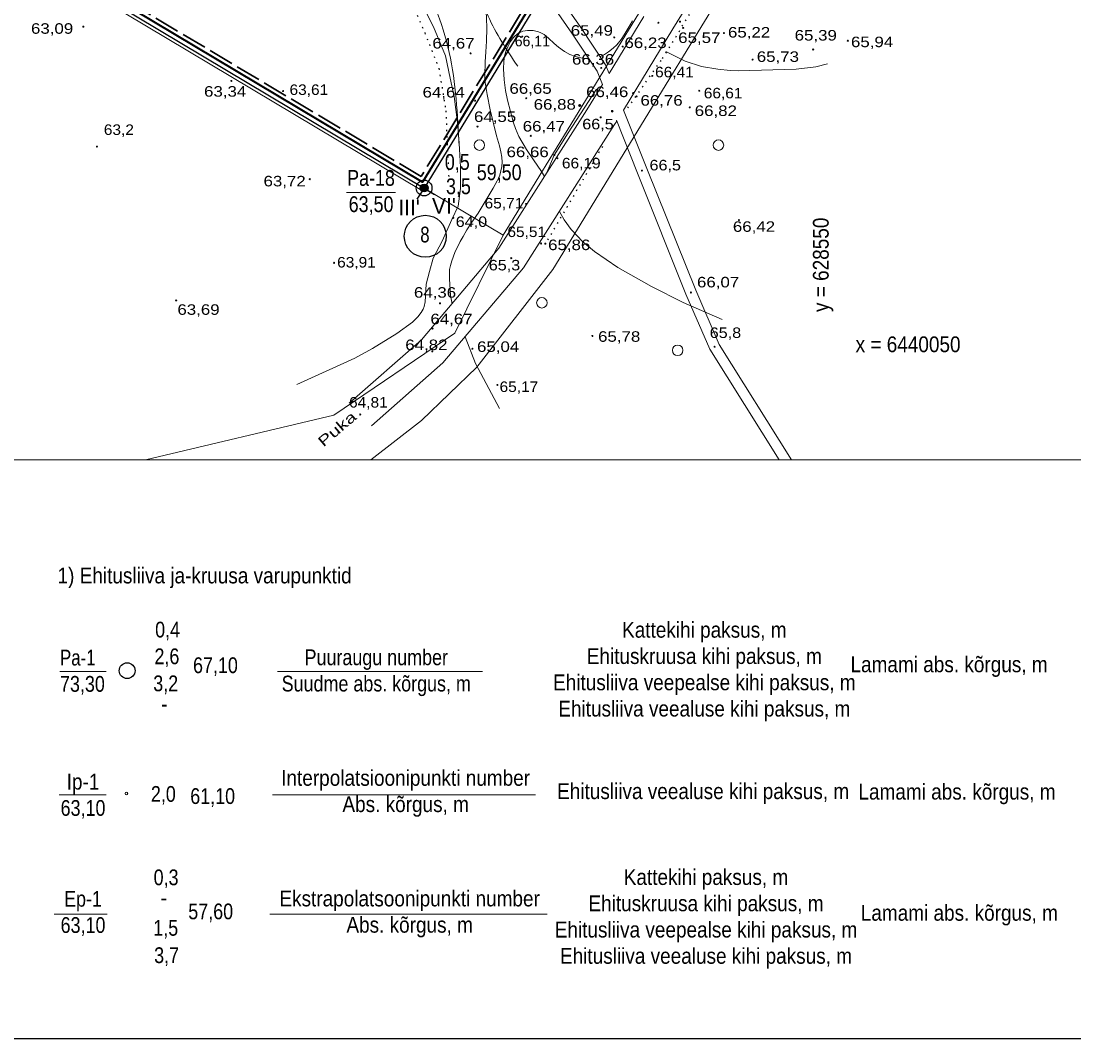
# Model space of a CAD drawing. Extents: x 628176 to 629009, y 6439913 to 6440496.
# Drawn here: x 628397.5 to 628597.9, y 6439918.5 to 6440112.2 of the extents above; entities that cross this region are included whole.
import ezdxf
from ezdxf.enums import TextEntityAlignment as Align

# ---------------------------------------------------------------- set-up
doc = ezdxf.new("R2010")
doc.units = 0
doc.header["$LTSCALE"] = 0.8
doc.header["$PDMODE"] = 32
doc.header["$PDSIZE"] = 0.4
for name, pattern in [('DOTTED', [1.5, 0.3, -1.2]), ('LONG_DASHED', [7.5, 6, -1.5]), ('MEDIUM_DASHED', [4.5, 3, -1.5])]:
    doc.linetypes.add(name, pattern=pattern)
for name, color, linetype, lineweight in [('1', 7, 'Continuous', 13), ('10', 7, 'Continuous', 25), ('11', 7, 'Continuous', 13), ('12', 7, 'Continuous', 13), ('14', 7, 'Continuous', 25), ('16', 7, 'Continuous', 13), ('21', 7, 'MEDIUM_DASHED', 35), ('3', 7, 'Continuous', 13), ('50', 7, 'Continuous', 13), ('6', 7, 'Continuous', 13)]:
    doc.layers.add(name, color=color, linetype=linetype, lineweight=lineweight)
doc.layers.add('4', color=7, linetype='Continuous')

msp = doc.modelspace()

# ---------------------------------------------------------------- hatches: boundary and pattern name
at = {"layer": '1'}
for points in [[(628409.4344, 6440111.0968, 1), (628409.2344, 6440111.0968, 1)], [(628518.8892, 6440111.8299, 1), (628518.6892, 6440111.8299, 1)], [(628523.0029, 6440112.0418, 1), (628522.8029, 6440112.0418, 1)], [(628523.6039, 6440110.8596, 1), (628523.4039, 6440110.8596, 1)], [(628492.973, 6440109.1947, 1), (628492.773, 6440109.1947, 1)], [(628510.4901, 6440109.0442, 1), (628510.2901, 6440109.0442, 1)], [(628531.3555, 6440109.875, 1), (628531.1555, 6440109.875, 1)], [(628554.9507, 6440108.4224, 1), (628554.7507, 6440108.4224, 1)], [(628512.0944, 6440107.305, 1), (628511.8944, 6440107.305, 1)], [(628548.348, 6440106.7428, 1), (628548.148, 6440106.7428, 1)], [(628483.1387, 6440106.0153, 1), (628482.9387, 6440106.0153, 1)], [(628536.8173, 6440104.8325, 1), (628536.6173, 6440104.8325, 1)], [(628508.02, 6440103.2332, 1), (628507.82, 6440103.2332, 1)], [(628437.6027, 6440100.7657, 1), (628437.4027, 6440100.7657, 1)], [(628517.7301, 6440101.7257, 1), (628517.5301, 6440101.7257, 1)], [(628447.4419, 6440098.8264, 1), (628447.2419, 6440098.8264, 1)], [(628514.0625, 6440098.4337, 1), (628513.8625, 6440098.4337, 1)], [(628526.6704, 6440098.8894, 1), (628526.4704, 6440098.8894, 1)], [(628483.9966, 6440097.0016, 1), (628483.7966, 6440097.0016, 1)], [(628493.7415, 6440097.4794, 1), (628493.5415, 6440097.4794, 1)], [(628514.7413, 6440097.8113, 1), (628514.5413, 6440097.8113, 1)], [(628503.9057, 6440096.0814, 1), (628503.7057, 6440096.0814, 1)], [(628510.1499, 6440094.9999, 1), (628509.8499, 6440094.9999, 1)], [(628524.8585, 6440095.7336, 1), (628524.6585, 6440095.7336, 1)], [(628507.9065, 6440093.8416, 1), (628507.7065, 6440093.8416, 1)], [(628484.4614, 6440092.0725, 1), (628484.2614, 6440092.0725, 1)], [(628494.6041, 6440090.3159, 1), (628494.4041, 6440090.3159, 1)], [(628412.0191, 6440088.2674, 1), (628411.8191, 6440088.2674, 1)], [(628499.0777, 6440086.6428, 1), (628498.8777, 6440086.6428, 1)], [(628499.6637, 6440086.0555, 1), (628499.4637, 6440086.0555, 1)], [(628515.7505, 6440083.7074, 1), (628515.5505, 6440083.7074, 1)], [(628452.5166, 6440082.0727, 1), (628452.3166, 6440082.0727, 1)], [(628493.6983, 6440077.3653, 1), (628493.4983, 6440077.3653, 1)], [(628479.858, 6440074.712, 1), (628479.658, 6440074.712, 1)], [(628534.2109, 6440074.2868, 1), (628534.0109, 6440074.2868, 1)], [(628496.5678, 6440069.833, 1), (628496.3678, 6440069.833, 1)], [(628497.371, 6440069.8013, 1), (628497.171, 6440069.8013, 1)], [(628457.1623, 6440066.1546, 1), (628456.9623, 6440066.1546, 1)], [(628490.8968, 6440067.0402, 1), (628490.6968, 6440067.0402, 1)], [(628525.0757, 6440060.5076, 1), (628524.8757, 6440060.5076, 1)], [(628427.0999, 6440058.9999, 1), (628426.8999, 6440058.9999, 1)], [(628477.3165, 6440058.4485, 1), (628477.1165, 6440058.4485, 1)], [(628475.9093, 6440053.6329, 1), (628475.7093, 6440053.6329, 1)], [(628506.3236, 6440052.2325, 1), (628506.1236, 6440052.2325, 1)], [(628529.582, 6440050.1756, 1), (628529.382, 6440050.1756, 1)], [(628475.8453, 6440049.3102, 1), (628475.6453, 6440049.3102, 1)], [(628483.4845, 6440049.8094, 1), (628483.2845, 6440049.8094, 1)], [(628488.2514, 6440042.9153, 1), (628488.0514, 6440042.9153, 1)], [(628462.1416, 6440037.2921, 1), (628461.9416, 6440037.2921, 1)]]:
    msp.add_hatch(color=256, dxfattribs=at).paths.add_polyline_path(points)
at = {"layer": '10'}
msp.add_hatch(color=256, dxfattribs=at).paths.add_polyline_path([(628474.9413, 6440080.3879, 1), (628473.4413, 6440080.3879, 1)])

# ---------------------------------------------------------------- linework, layer by layer
at = {"layer": '1'}
for p, q in [((628534.28, 6440131.41), (628521.55, 6440110.66)), ((628496.83, 6440121.22), (628503.9, 6440111.11)), ((628495.17, 6440120.11), (628502.32, 6440109.88)), ((628516.03, 6440113), (628509.39, 6440102.16)), ((628503.9, 6440111.11), (628508.73, 6440103.82)), ((628521.55, 6440110.66), (628512.15, 6440095.22)), ((628502.32, 6440109.88), (628507.11, 6440102.65)), ((628508.12, 6440100.09), (628507.11, 6440102.65)), ((628509.39, 6440102.16), (628508.73, 6440103.82)), ((628501.63, 6440090.9), (628507.01, 6440099.21)), ((628508.12, 6440100.09), (628505.15, 6440095.24)), ((628503.81, 6440096.08), (628503.81, 6440096.33)), ((628505.15, 6440095.24), (628488.45, 6440068.91)), ((628503.81, 6440096.08), (628503.56, 6440096.08)), ((628503.81, 6440096.08), (628504.06, 6440096.08)), ((628503.81, 6440096.08), (628503.81, 6440095.83)), ((628516.58, 6440084.08), (628512.15, 6440095.22)), ((628510.46, 6440092.45), (628493.14, 6440065.17)), ((628510.87, 6440093.12), (628510.46, 6440092.45)), ((628514.79, 6440083.2), (628510.81, 6440093.28)), ((628501.63, 6440090.9), (628498.98, 6440086.64)), ((628498.98, 6440086.64), (628497.42, 6440083.05)), ((628524.03, 6440060.19), (628514.79, 6440083.2)), ((628525.89, 6440060.92), (628516.58, 6440084.08)), ((628488.45, 6440068.91), (628473.7, 6440051.51)), ((628493.14, 6440065.17), (628477.79, 6440047.11)), ((628528.58, 6440049.74), (628524.03, 6440060.19)), ((628530.38, 6440050.61), (628525.89, 6440060.92)), ((628473.7, 6440051.51), (628459.93, 6440039.43)), ((628544.1, 6440028.67), (628530.38, 6440050.61)), ((628541.76, 6440028.67), (628528.58, 6440049.74)), ((628477.79, 6440047.11), (628464.15, 6440035.16))]:
    msp.add_line(p, q, dxfattribs=at)
at = {"layer": '1', "linetype": 'DOTTED', "lineweight": 25}
for p, q in [((628519.58, 6440105.02), (628527.09, 6440117.27)), ((628512.96, 6440095.64), (628519.58, 6440105.02)), ((628508.15, 6440088.29), (628497.27, 6440069.8))]:
    msp.add_line(p, q, dxfattribs=at)
msp.add_lwpolyline([(628472.43, 6440114.37), (628474.33, 6440109.9), (628477.01, 6440103.1), (628478.35, 6440095.06), (628478.57, 6440088.81), (628478.91, 6440081.78)], dxfattribs=at)
at = {"layer": '1'}
for centre, radius in [((628409.3344, 6440111.0968), 0.1), ((628518.7892, 6440111.8299), 0.1), ((628522.9029, 6440112.0418), 0.1), ((628523.5039, 6440110.8596), 0.1), ((628492.873, 6440109.1947), 0.1), ((628510.3901, 6440109.0442), 0.1), ((628531.2555, 6440109.875), 0.1), ((628554.8507, 6440108.4224), 0.1), ((628511.9944, 6440107.305), 0.1), ((628548.248, 6440106.7428), 0.1), ((628483.0387, 6440106.0153), 0.1), ((628536.7173, 6440104.8325), 0.1), ((628507.92, 6440103.2332), 0.1), ((628437.5027, 6440100.7657), 0.1), ((628517.6301, 6440101.7257), 0.1), ((628447.3419, 6440098.8264), 0.1), ((628513.9625, 6440098.4337), 0.1), ((628526.5704, 6440098.8894), 0.1), ((628483.8966, 6440097.0016), 0.1), ((628493.6415, 6440097.4794), 0.1), ((628514.6413, 6440097.8113), 0.1), ((628503.8057, 6440096.0814), 0.1), ((628509.9999, 6440094.9999), 0.15), ((628524.7585, 6440095.7336), 0.1), ((628507.8065, 6440093.8416), 0.1), ((628484.3614, 6440092.0725), 0.1), ((628494.5041, 6440090.3159), 0.1), ((628411.9191, 6440088.2674), 0.1), ((628484.7198, 6440088.5447), 1), ((628530.2203, 6440088.5447), 1), ((628498.9777, 6440086.6428), 0.1), ((628499.5637, 6440086.0555), 0.1), ((628515.6505, 6440083.7074), 0.1), ((628452.4166, 6440082.0727), 0.1), ((628493.5983, 6440077.3653), 0.1), ((628479.758, 6440074.712), 0.1), ((628534.1109, 6440074.2868), 0.1), ((628496.4678, 6440069.833), 0.1), ((628497.271, 6440069.8013), 0.1), ((628457.0623, 6440066.1546), 0.1), ((628490.7968, 6440067.0402), 0.1), ((628524.9757, 6440060.5076), 0.1), ((628426.9999, 6440058.9999), 0.1), ((628477.2165, 6440058.4485), 0.1), ((628496.612, 6440058.5557), 1), ((628475.8093, 6440053.6329), 0.1), ((628506.2236, 6440052.2325), 0.1), ((628522.4645, 6440049.5074), 1), ((628529.482, 6440050.1756), 0.1), ((628475.7453, 6440049.3102), 0.1), ((628483.3845, 6440049.8094), 0.1), ((628488.1514, 6440042.9153), 0.1), ((628462.0416, 6440037.2921), 0.1)]:
    msp.add_circle(centre, radius, dxfattribs=at)
at = {"layer": '10'}
for centre, radius in [((628474.1913, 6440080.3879), 0.75), ((628474.4192, 6440071.2019), 4)]:
    msp.add_circle(centre, radius, dxfattribs=at)
at = {"layer": '11'}
msp.add_lwpolyline([(628497.5, 6440118.54), (628474.19, 6440080.39), (628272.25, 6440200.89), (628236.02, 6440221.83), (628393.19, 6440398.39)], dxfattribs=at)
msp.add_point((628503.81, 6440096.08), dxfattribs=at)
at = {"layer": '12'}
msp.add_line((628459.44, 6440079.54), (628468.78, 6440079.54), dxfattribs=at)
at = {"layer": '12', "lineweight": 25}
msp.add_circle((628474.1913, 6440080.3879), 1.5, dxfattribs=at)
at = {"layer": '14'}
msp.add_line((628474.19, 6440080.39), (628472.82, 6440078.24), dxfattribs=at)
for points in [[(628648.46, 6440349.59), (628617.39, 6440307.28), (628547.63, 6440210.77), (628497.5, 6440118.54), (628474.19, 6440080.39)], [(628267.86, 6440203.3), (628311.23, 6440177.63), (628327.53, 6440167.88), (628373.06, 6440140.73), (628474.19, 6440080.39), (628476.16, 6440079.17)]]:
    msp.add_lwpolyline(points, dxfattribs=at)
at = {"layer": '16'}
for points in [[(628409.9, 6440254.58), (628412.29, 6440252.6), (628420.3, 6440245.33), (628427.75, 6440237.7), (628436.13, 6440222.98), (628444.52, 6440204.92), (628447.68, 6440184.24), (628451.78, 6440164.12), (628460.72, 6440143.45), (628472.64, 6440122.77), (628478.97, 6440106.2), (628480.84, 6440088.32)], [(628435.66, 6440253.61), (628435.76, 6440253.53), (628440.6, 6440249.8), (628446.19, 6440242.17), (628451.59, 6440233.41), (628456.06, 6440220.19), (628460.16, 6440203.24), (628465, 6440185.73), (628472.27, 6440163.38), (628475.81, 6440154.44), (628479.91, 6440135.81), (628483.63, 6440121.84), (628486.42, 6440113.09), (628492.01, 6440103.59)]]:
    msp.add_spline(points, degree=3, dxfattribs=at)
at = {"layer": '21', "linetype": 'Continuous', "lineweight": 40}
msp.add_lwpolyline([(628496.82, 6440118.96), (628473.92, 6440081.48), (628320.39, 6440173.09)], dxfattribs=at)
at = {"layer": '21', "linetype": 'LONG_DASHED'}
msp.add_lwpolyline([(628496.07, 6440119.27), (628473.65, 6440082.57), (628323.6, 6440172.11)], dxfattribs=at)
at = {"layer": '3'}
for p, q in [((628486.11, 6440110.8), (628486.04, 6440108.32)), ((628490.66, 6440108.25), (628490.96, 6440108.69)), ((628512.29, 6440109.51), (628511.72, 6440108.67)), ((628489.82, 6440106.54), (628489.58, 6440105.76)), ((628490.13, 6440107.27), (628489.82, 6440106.54)), ((628520.23, 6440106.38), (628523.91, 6440104.55)), ((628485.8, 6440104.38), (628485.73, 6440101.72)), ((628507.87, 6440105.45), (628507.68, 6440105.4)), ((628485.84, 6440100.47), (628485.73, 6440101.72)), ((628486.2, 6440098.2), (628485.84, 6440100.47)), ((628486.78, 6440095.27), (628486.2, 6440098.2)), ((628488, 6440090.31), (628486.78, 6440095.27)), ((628510, 6440095), (628510, 6440095.15)), ((628510, 6440095), (628510.15, 6440095)), ((628510, 6440095), (628510, 6440094.85)), ((628491.58, 6440091.69), (628491.2, 6440092.79)), ((628488.54, 6440088.39), (628488, 6440090.31)), ((628488.81, 6440087.29), (628488.54, 6440088.39)), ((628488.81, 6440087.29), (628488.97, 6440086.23)), ((628496.56, 6440083.5), (628497.12, 6440082.58)), ((628500.87, 6440074.36), (628499.98, 6440075.94)), ((628479.45, 6440066.55), (628479.2, 6440065.66)), ((628479, 6440063.79), (628479.06, 6440064.88)), ((628479.2, 6440065.66), (628479.06, 6440064.88)), ((628479, 6440063.79), (628479, 6440063.08)), ((628479.21, 6440059.95), (628479, 6440063.08)), ((628474.23, 6440057.86), (628474.38, 6440058.7)), ((628479.21, 6440059.95), (628479.52, 6440058.38)), ((628473.66, 6440056.69), (628473, 6440055.87)), ((628461, 6440048), (628450, 6440043))]:
    msp.add_line(p, q, dxfattribs=at)
for points in [[(628472.91, 6440117.11), (628476, 6440111.03), (628478.24, 6440105.55), (628479.15, 6440101.29), (628479.91, 6440097.79), (628480.52, 6440092.86), (628480.87, 6440088.91), (628481.1, 6440084.38), (628481.13, 6440080.31), (628480.67, 6440076.96), (628479.45, 6440074.37), (628477.63, 6440070.27), (628475.95, 6440067.07), (628475.19, 6440064.49), (628474.59, 6440062.06), (628474.38, 6440058.7)], [(628486.11, 6440110.8), (628486.09, 6440112.69), (628485.97, 6440115.2), (628485.84, 6440115.95)], [(628495.87, 6440110.15), (628495.49, 6440110.25), (628494.96, 6440110.34), (628494.34, 6440110.38), (628493.9, 6440110.35), (628493.41, 6440110.3), (628493, 6440110.21), (628492.61, 6440110.07), (628492.24, 6440109.89), (628491.85, 6440109.63), (628491.53, 6440109.36), (628491.2, 6440109.02), (628490.96, 6440108.69)], [(628513.84, 6440112.23), (628513.44, 6440111.43), (628512.29, 6440109.51)], [(628485.8, 6440104.38), (628485.95, 6440106.3), (628486.04, 6440108.32)], [(628495.87, 6440110.15), (628496.55, 6440109.86), (628497.03, 6440109.58)], [(628504.87, 6440105.02), (628503.67, 6440105.22), (628503.03, 6440105.39), (628501.95, 6440105.79), (628500.93, 6440106.35), (628499.8, 6440107.19), (628498.93, 6440107.91), (628497.85, 6440108.91), (628497.03, 6440109.58)], [(628511.72, 6440108.67), (628510.87, 6440107.64), (628510.19, 6440106.97), (628509.29, 6440106.27)], [(628490.66, 6440108.25), (628490.39, 6440107.79), (628490.13, 6440107.27)], [(628489.58, 6440105.76), (628489.43, 6440105.06), (628489.37, 6440104.45), (628489.32, 6440103.05), (628489.42, 6440100.98), (628489.71, 6440098.97), (628490.1, 6440097.12), (628491.2, 6440092.79)], [(628505.52, 6440105.04), (628505.4, 6440105.03), (628504.87, 6440105.02)], [(628509.29, 6440106.27), (628508.54, 6440105.78), (628507.87, 6440105.45)], [(628530.09, 6440103), (628527, 6440103.51), (628523.91, 6440104.55)], [(628530.09, 6440103), (628532.43, 6440102.76), (628534, 6440102.66)], [(628534, 6440102.66), (628545, 6440103), (628548.76, 6440103.44), (628551, 6440104)], [(628491.58, 6440091.69), (628492.24, 6440090.22), (628493.71, 6440087.69)], [(628496.56, 6440083.5), (628494.99, 6440085.73), (628493.71, 6440087.69)], [(628479.45, 6440066.55), (628480.06, 6440068.14), (628481.07, 6440070.2), (628481.63, 6440071.18), (628482.35, 6440072.4), (628483.18, 6440073.71), (628483.73, 6440074.52), (628484.46, 6440075.63), (628486.03, 6440078.11), (628487.35, 6440080.39), (628488.09, 6440081.75), (628488.34, 6440082.25), (628488.59, 6440082.86), (628488.82, 6440083.63), (628488.99, 6440084.5), (628489.03, 6440085.3), (628488.97, 6440086.23)], [(628506.6, 6440068.28), (628504.39, 6440070.17), (628502.2, 6440072.49), (628500.87, 6440074.36)], [(628530.92, 6440055.38), (628523.5, 6440058.63), (628517.48, 6440061.65), (628511.1, 6440065.24), (628506.6, 6440068.28)], [(628474.23, 6440057.86), (628474.02, 6440057.32), (628473.66, 6440056.69)], [(628473, 6440055.87), (628471.96, 6440054.87), (628469, 6440052.73), (628464.36, 6440049.83), (628461, 6440048)], [(628481.99, 6440052.06), (628484, 6440047), (628488.56, 6440038.41)]]:
    msp.add_lwpolyline(points, dxfattribs=at)
at = {"layer": '50'}
for p, q in [((628404.83, 6439988.36), (628413.68, 6439988.36)), ((628446.3, 6439988.36), (628485.34, 6439988.36)), ((628404.7, 6439964.95), (628413.65, 6439964.95)), ((628445.32, 6439964.95), (628495.41, 6439964.95)), ((628403.78, 6439942.23), (628413.88, 6439942.23)), ((628444.86, 6439942.23), (628497.64, 6439942.23))]:
    msp.add_line(p, q, dxfattribs=at)
at = {"layer": '50', "lineweight": 25}
msp.add_lwpolyline([(628178.27, 6440495.9), (629008.51, 6440495.9), (629008.51, 6439918.47), (628178.27, 6439918.47)], close=True, dxfattribs=at)
at = {"layer": '50'}
msp.add_lwpolyline([(628214.18, 6440472.45), (628760.23, 6440472.45), (628760.23, 6440028.67), (628214.18, 6440028.67)], close=True, dxfattribs=at)
at = {"layer": '50', "lineweight": 25}
msp.add_circle((628417.6668, 6439988.5374), 1.5, dxfattribs=at)
at = {"layer": '50'}
msp.add_circle((628417.5253, 6439965.181), 0.25, dxfattribs=at)
at = {"layer": '6'}
msp.add_line((628489.22, 6440071.42), (628474.19, 6440080.39), dxfattribs=at)
for points in [[(628713.84, 6440420.66), (628737.18, 6440419.44), (628678.6, 6440359.86), (628654.6, 6440328.98), (628627.14, 6440290.88), (628627.14, 6440290.88), (628627.14, 6440290.88), (628562.66, 6440201.7), (628536.24, 6440148.38), (628489.22, 6440071.42), (628480.02, 6440052.78), (628457.03, 6440037.16), (628421.17, 6440028.67)], [(628753.89, 6440420.62), (628687.68, 6440352.8), (628636.46, 6440284.16), (628572.54, 6440195.74), (628546.32, 6440142.82), (628546.32, 6440142.82), (628546.32, 6440142.82), (628498.7, 6440064.9), (628484.24, 6440046.28), (628473.72, 6440036.18), (628464.05, 6440028.67)], [(628473.77, 6440079.94), (628271.95, 6440200.37), (628235.6, 6440221.38)]]:
    msp.add_lwpolyline(points, dxfattribs=at)

# ---------------------------------------------------------------- texts
at = {"layer": '1'}
for s, width, p in [('63,09', 1.2, (628399.37, 6440109.74)), ('65,49', 1.2, (628502.11, 6440109.37)), ('65,22', 1.2, (628532.04, 6440109.02)), ('65,39', 1.2, (628544.73, 6440108.45)), ('64,67', 1.2, (628475.77, 6440106.93)), ('66,23', 1.2, (628512.33, 6440107.02)), ('65,57', 1.2, (628522.56, 6440107.99)), ('65,94', 1.2, (628555.45, 6440107.19)), ('65,73', 1.2, (628537.52, 6440104.39)), ('66,36', 1.2, (628502.34, 6440103.87)), ('66,41', 1.1, (628518.16, 6440101.45)), ('66,65', 1.2, (628490.44, 6440098.32)), ('63,34', 1.2, (628432.31, 6440097.77)), ('63,61', 1.1, (628448.58, 6440098.1)), ('64,64', 1.2, (628473.9, 6440097.61)), ('66,46', 1.2, (628505.04, 6440097.69)), ('66,61', 1.1, (628527.43, 6440097.45)), ('66,88', 1.2, (628495.05, 6440095.3)), ('66,76', 1.2, (628515.38, 6440096.06)), ('64,55', 1.2, (628483.69, 6440092.96)), ('66,82', 1.2, (628525.71, 6440094.09)), ('63,2', 1.1, (628413.23, 6440090.49)), ('66,47', 1.2, (628492.97, 6440091.14)), ('66,5', 1.15, (628504.3, 6440091.55)), ('66,66', 1.2, (628489.89, 6440086.26)), ('66,19', 1.1, (628500.43, 6440084.12)), ('66,5', 1.15, (628517.1, 6440083.74)), ('63,72', 1.2, (628443.63, 6440080.7)), ('65,71', 1.1, (628485.71, 6440076.5)), ('64,0', 1.15, (628480.21, 6440072.98)), ('65,51', 1.1, (628490.05, 6440071.06)), ('66,42', 1.2, (628532.97, 6440072.05)), ('65,86', 1.2, (628497.8, 6440068.57)), ('63,91', 1.1, (628457.64, 6440065.26)), ('65,3', 1.15, (628486.5, 6440064.71)), ('66,07', 1.2, (628526.14, 6440061.48)), ('64,36', 1.2, (628472.26, 6440059.52)), ('63,69', 1.2, (628427.24, 6440056.26)), ('64,67', 1.2, (628475.4, 6440054.47)), ('65,78', 1.2, (628507.31, 6440051.13)), ('65,8', 1.15, (628528.56, 6440051.85)), ('64,82', 1.2, (628470.61, 6440049.55)), ('65,04', 1.2, (628484.27, 6440049.2)), ('65,17', 1.1, (628488.56, 6440041.58)), ('64,81', 1.1, (628459.91, 6440038.61))]:
    msp.add_text(s, height=2, dxfattribs=dict(at, width=width)).set_placement(p)
msp.add_text('66,11', height=2, dxfattribs=at).set_placement((628491.45, 6440107.35))
at = {"layer": '1', "width": 1.4}
msp.add_text('Puka', height=2, rotation=40.505, dxfattribs=at).set_placement((628455.04, 6440031.01))
at = {"layer": '10', "width": 0.8}
msp.add_text('8', height=3, dxfattribs=at).set_placement((628474.35, 6440070.03), align=Align.CENTER)
at = {"layer": '11', "width": 0.85}
msp.add_text('0,5', height=3, dxfattribs=at).set_placement((628480.51, 6440083.84), align=Align.CENTER)
at = {"layer": '12', "width": 0.85}
for s, p in [('59,50', (628488.485, 6440081.88)), ('Pa-18', (628464.095, 6440080.81)), ('3,5', (628480.735, 6440079.21)), ('63,50', (628464.105, 6440075.81))]:
    msp.add_text(s, height=3, dxfattribs=at).set_placement(p, align=Align.CENTER)
at = {"layer": '14'}
for s, p in [("VI'", (628477.97, 6440075.5)), ("III'", (628471.34, 6440075.16))]:
    msp.add_text(s, height=3, dxfattribs=at).set_placement(p, align=Align.CENTER)
at = {"layer": '4', "width": 0.9}
msp.add_text('y = 628550', height=3, rotation=90, dxfattribs=at).set_placement((628551.2, 6440056.79))
msp.add_text('x = 6440050', height=3, dxfattribs=at).set_placement((628556.33, 6440049.15))
at = {"layer": '50'}
for s, width, p in [('1) Ehitusliiva ja-kruusa varupunktid', 0.9, (628404.42, 6440005.15)), ('0,4', 0.85, (628423, 6439994.86)), ('Pa-1', 0.8, (628404.89, 6439989.53)), ('2,6', 0.85, (628422.87, 6439989.78)), ('67,10', 0.85, (628430.21, 6439988.08)), ('73,30', 0.85, (628404.89, 6439984.53)), ('3,2', 0.85, (628422.64, 6439984.63)), ('-', 0.9, (628424.12, 6439980.73)), ('2,0', 0.85, (628422.19, 6439963.59)), ('61,10', 0.85, (628429.68, 6439963.18)), ('0,3', 0.85, (628422.71, 6439947.72)), ('-', 0.95, (628424.03, 6439943.85)), ('57,60', 0.85, (628429.31, 6439941.24)), ('1,5', 0.85, (628422.65, 6439938.11)), ('3,7', 0.85, (628422.81, 6439932.9))]:
    msp.add_text(s, height=3, dxfattribs=dict(at, width=width)).set_placement(p)
for s, width, p in [('Kattekihi paksus, m', 0.9, (628527.53, 6439994.82)), ('Puuraugu number', 0.85, (628465.09, 6439989.59)), ('Ehituskruusa kihi paksus, m', 0.9, (628527.535, 6439989.82)), ('Lamami abs. kõrgus, m', 0.9, (628574.12, 6439988.25)), ('Suudme abs. kõrgus, m', 0.85, (628465.09, 6439984.59)), ('Ehitusliiva veepealse kihi paksus, m', 0.9, (628527.535, 6439984.82)), ('Ehitusliiva veealuse kihi paksus, m', 0.9, (628527.53, 6439979.82)), ('Ip-1', 0.9, (628409.27, 6439965.92)), ('Interpolatsioonipunkti number', 0.9, (628470.68, 6439966.64)), ('Ehitusliiva veealuse kihi paksus, m', 0.9, (628527.31, 6439964.11)), ('Lamami abs. kõrgus, m', 0.9, (628575.63, 6439964.02)), ('Abs. kõrgus, m', 0.9, (628470.685, 6439961.64)), ('63,10', 0.85, (628409.27, 6439960.92)), ('Kattekihi paksus, m', 0.9, (628527.85, 6439947.77)), ('Ep-1', 0.85, (628409.27, 6439943.64)), ('Ekstrapolatsoonipunkti number', 0.9, (628471.44, 6439943.69)), ('Ehituskruusa kihi paksus, m', 0.9, (628527.855, 6439942.77)), ('Lamami abs. kõrgus, m', 0.9, (628576.075, 6439940.96)), ('63,10', 0.85, (628409.27, 6439938.64)), ('Abs. kõrgus, m', 0.9, (628471.445, 6439938.69)), ('Ehitusliiva veepealse kihi paksus, m', 0.9, (628527.855, 6439937.77)), ('Ehitusliiva veealuse kihi paksus, m', 0.9, (628527.85, 6439932.77))]:
    msp.add_text(s, height=3, dxfattribs=dict(at, width=width)).set_placement(p, align=Align.CENTER)

doc.saveas('drawing.dxf')
